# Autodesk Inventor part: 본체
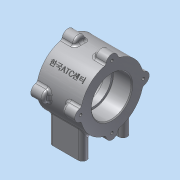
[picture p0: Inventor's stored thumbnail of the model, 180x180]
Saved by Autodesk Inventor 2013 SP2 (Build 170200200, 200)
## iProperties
Created: 2015-03
Part Number: 본체
Material: 알루미늄 6061
Document SubType Name: Modeling
Designer: dgall
Density: 2.71 g/cm^3
Author: dgall
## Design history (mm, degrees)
sketch "스케치1"
  geometry: C1 r 37 at (0, 0); 1 further point
  constraints: 1 centre point, 1 coincident
  dimensions: "d0" = 74 diameter of C1
extrude "돌출1" new body sketch "스케치1" stored distance "d2" = 52; taper "d3" = 0 deg
sketch "스케치2"
  geometry: A1 r 37 centre (0, 0) between (0, 37) and (-6.969, 36.338) reference; A2 r 7 centre (0, 37) between (6.969, 36.338) and (-6.969, 36.338)
  constraints: 5 point on circle, 1 centre point, 1 vertical alignment
  dimensions: "d4" = 7 radius of A2
extrude "돌출2" join sketch "스케치2" distance "d6" = 15; taper "d7" = 0 deg
sketch "스케치3"
  geometry: L1 (-19, -20)-(-29, -20); L2 (-29, -20)-(-29, 20); L3 (-29, 20)-(-19, 20); L4 (-19, 20)-(-19, -20); 3 further points
  constraints: 8 end point, 2 midpoint, 2 parallel, 1 horizontal, 1 horizontal alignment, 1 perpendicular
  dimensions: "d11" = 10 distance of L1.start L1.end; "d13" = 40 distance of L1.end L2.end; "d14" = 24 horizontal distance of point (-24, 20) point (0, 0)
extrude "돌출3" join sketch "스케치3" distance "d15" = 56; taper "d16" = 0 deg
sketch "스케치4"
  geometry: L1 (36.338, 26)-(6.969, 26) reference; L2 (6.969, -26)-(36.338, -26) reference; L3 (7, 26)-(-7, 26) reference; L4 (7, -26)-(-7, -26) reference; L5 (0, 26)-(0, -26); L6 (23.5, 26)-(23.5, 4); L7 (23.5, 4)-(21, 4); L8 (21, 4)-(21, -4); L9 (21, -4)-(23.5, -4); L10 (23.5, -4)-(23.5, -26); 3 further points
  constraints: 12 end point, 3 parallel, 2 midpoint, 2 perpendicular, 2 point on line, 1 collinear, 1 vertical alignment
  dimensions: "d17" = 47 diameter of L6 L5; "d19" = 47 diameter of L10 L5; "d20" = 42 diameter of L8 L5; "d21" = 22 distance of L6.start L6.end; "d22" = 22 distance of L9.end L10.end
revolve "회전1" sketch "스케치4" stored, may be unused: angle "d23" = 90 deg
hole "구멍1" diameter "d26" = 3.242; stored, may be unused: countersink angle "d30" = 90 deg, drill point angle "d32" = 118 deg; dims "d24" = 10, "d25" = 10, "d27" = 8, "d28" = 4, "d29" = 2, "d31" = 11
sketch "스케치5"
  geometry: L1 (29, 20)-(19, 20) reference; 3 further points
  constraints: 1 midpoint, 1 vertical alignment
  dimensions: "d36" = 5 distance from line of point (24, 15) L1
hole "구멍2" sketch "스케치5" at (24, 15) diameter "d37" = 4.134; stored, may be unused: countersink angle "d41" = 90 deg, drill point angle "d43" = 118 deg; dims "d38" = 6, "d39" = 4, "d40" = 2, "d42" = 8
sketch "스케치6"
  geometry: L1 (0, 0)-(-26.163, 26.163); L2 (0, 0)-(-44, 0); C1 r 1.621 at (37, 0) reference; C2 r 1.621 at (0, -37) reference; C3 r 1.621 at (-37, 0) reference; C4 r 1.621 at (0, 37) reference; C5 r 23.5 at (0, 0) reference; A1 r 37 centre (0, 0) between (-6.969, 36.338) and (-36.338, 6.969) reference; A2 r 7 centre (-37, 0) between (-36.338, 6.969) and (-36.338, -6.969) reference; A3 r 37 centre (0, 0) between (-36.338, -6.969) and (-6.969, -36.338) reference; A4 r 7 centre (0, -37) between (-6.969, -36.338) and (6.969, -36.338) reference; A5 r 37 centre (0, 0) between (6.969, -36.338) and (36.338, -6.969) reference; A6 r 7 centre (37, 0) between (36.338, -6.969) and (36.338, 6.969) reference; A7 r 37 centre (0, 0) between (36.338, 6.969) and (6.969, 36.338) reference; A8 r 7 centre (0, 37) between (6.969, 36.338) and (-6.969, 36.338) reference
  constraints: 4 end point, 2 point on circle
  dimensions: "d46" = 45 deg angle of L1 L2
node "작업 평면3"
sketch "스케치7"
  geometry: L1 (20.767, 0)-(-20.767, 0) reference; 3 further points
  constraints: 1 coincident, 1 midpoint, 1 vertical alignment, 1 other
feature "엠보싱1" sketch "스케치7" dims "d47" = 0.5, "d48" = 0
fillet "모깎기1" dims "d49" = 5, "d50" = 3, "d52" = 0.3
fillet "모깎기2" dims "d51" = 3
chamfer "모따기1" distance "d53" = 1; stored, may be unused: second distance "d54" = 2, angle "d55" = 45 deg
node "솔리드1"
pattern_circular "원형 패턴1" dims angle "d9" = 360 deg
mirror "대칭1"
mirror "대칭2"
pattern_circular "원형 패턴2" dims angle "d34" = 360 deg
mirror "대칭3"
mirror "대칭4"
mirror "대칭5"
